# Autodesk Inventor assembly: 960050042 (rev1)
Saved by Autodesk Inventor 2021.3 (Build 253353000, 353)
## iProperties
Created: 2023-03
Part Number: 960050042 (rev1)
Document SubType Name: Assembly
Designer: AdminForWorker
Title: 960050042 (rev1) v2
Author: AdminForWorker
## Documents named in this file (2)
- z:\worker\convert-fusion-r08-cosv3\tmp\job-1\3553\output\files\82b4d9ad-b575-4129-b9ca-4964d6b72adf\960050042 (rev1) v2.iam
- z:\worker\convert-fusion-r08-cosv3\tmp\job-1\3553\output\files\82b4d9ad-b575-4129-b9ca-4964d6b72adf\960050042 (rev1).ipt
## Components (1 placed, 1 different names)
1. 960050042 (rev1):1
